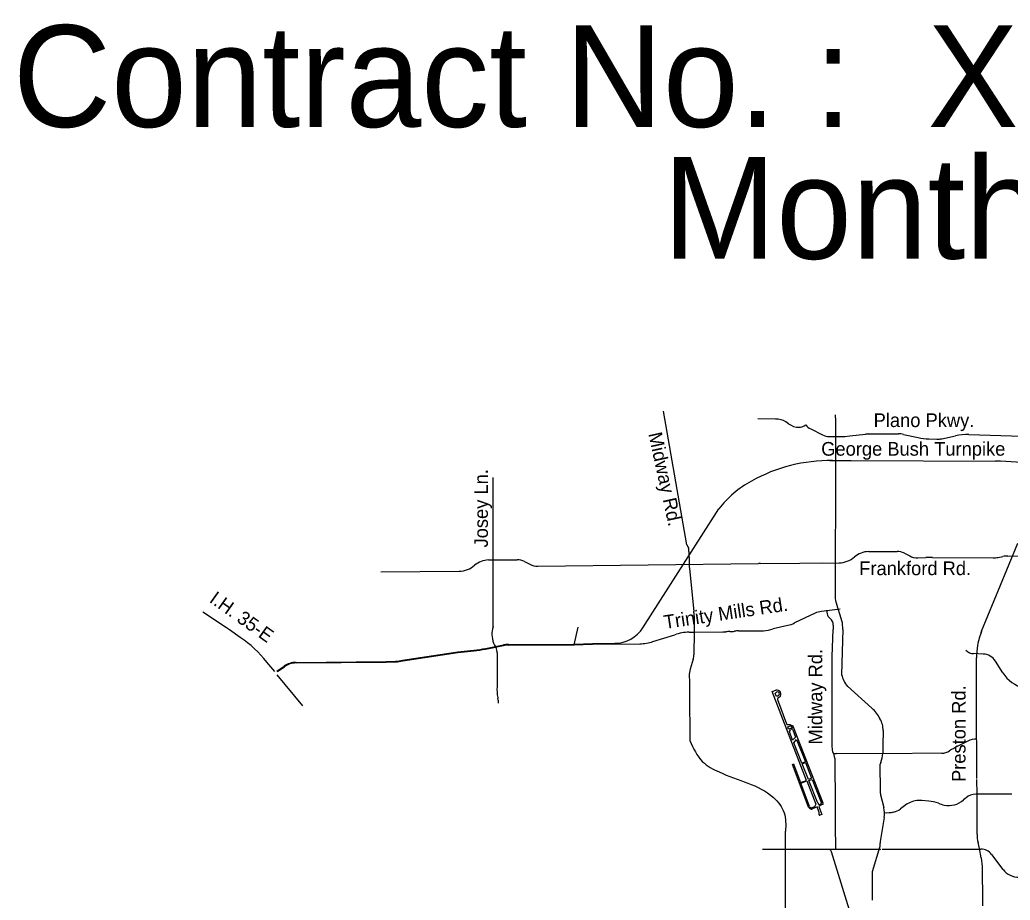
# Model space of a CAD drawing. Extents: x 105094 to 105814, y -291615 to -291123.
# Drawn here: x 105360.5 to 105448.1, y -291368.5 to -291290.6 of the extents above; entities that cross this region are included whole.
import ezdxf

# ---------------------------------------------------------------- set-up
doc = ezdxf.new("R2010")
doc.units = 0
doc.layers.add('G_BORDER', color=7, linetype='Continuous')
doc.layers.add('G_MAP', color=7, linetype='Continuous')

msp = doc.modelspace()

# ---------------------------------------------------------------- linework, layer by layer
at = {"layer": 'G_MAP'}
for p, q in [((105419.494, -291337.073), (105417.442, -291325.252)), ((105430.458, -291326.814), (105431.511, -291327.347)), ((105435.604, -291327.26), (105438.208, -291327.245)), ((105438.659, -291327.293), (105439.969, -291327.583)), ((105444.437, -291327.303), (105451.201, -291327.501)), ((105440.916, -291327.699), (105441.614, -291327.716)), ((105442.054, -291327.675), (105443.264, -291327.413)), ((105432.98, -291328.9), (105432.98, -291328.902)), ((105402.349, -291344.321), (105402.349, -291331.116)), ((105415.604, -291344.408), (105422.316, -291333.896)), ((105419.494, -291337.073), (105419.636, -291337.335)), ((105419.674, -291337.655), (105419.7, -291338.562)), ((105435.564, -291337.666), (105438.093, -291337.642)), ((105438.742, -291337.801), (105439.21, -291338.05)), ((105401.951, -291338.405), (105404.48, -291338.382)), ((105405.129, -291338.54), (105405.597, -291338.789)), ((105406.323, -291338.958), (105425.832, -291338.724)), ((105426.02, -291338.708), (105432.96, -291338.658)), ((105431.463, -291338.643), (105431.463, -291338.626)), ((105439.935, -291338.219), (105440.635, -291338.197)), ((105441.227, -291338.189), (105446.586, -291338.213)), ((105447.024, -291338.176), (105447.458, -291338.099)), ((105447.891, -291338.057), (105449.27, -291338.037)), ((105392.407, -291339.447), (105399.347, -291339.397)), ((105419.716, -291339.166), (105420.114, -291342.961)), ((105378.755, -291344.414), (105376.682, -291343.031)), ((105430.841, -291343.124), (105429.009, -291343.982)), ((105433.058, -291342.746), (105431.403, -291342.961)), ((105431.857, -291342.859), (105431.917, -291343.182)), ((105379.03, -291344.591), (105378.755, -291344.414)), ((105379.983, -291345.256), (105379.03, -291344.591)), ((105402.364, -291344.282), (105402.349, -291344.321)), ((105424.066, -291344.676), (105426.265, -291344.669)), ((105428.417, -291344.189), (105427.142, -291344.492)), ((105432.441, -291344.179), (105432.427, -291344.549)), ((105433.294, -291344.567), (105433.191, -291348.542)), ((105445.578, -291344.69), (105445.527, -291344.888)), ((105402.254, -291345.03), (105402.293, -291345.395)), ((105416.496, -291345.633), (105418.423, -291345.016)), ((105401.672, -291346.239), (105403.264, -291345.926)), ((105401.682, -291346.294), (105403.275, -291345.98)), ((105402.6, -291346.149), (105402.696, -291346.49)), ((105402.716, -291346.633), (105402.71, -291349.633)), ((105403.72, -291345.889), (105409.47, -291345.848)), ((105383.031, -291348.279), (105382.331, -291347.446)), ((105420.065, -291347.178), (105419.79, -291348.071)), ((105445.715, -291346.727), (105444.865, -291346.693)), ((105447.448, -291348.381), (105446.796, -291347.35)), ((105383.232, -291348.24), (105383.858, -291347.801)), ((105383.264, -291348.286), (105383.89, -291347.846)), ((105432.318, -291347.86), (105432.331, -291354.963)), ((105385.508, -291351.319), (105383.251, -291348.557)), ((105433.702, -291349.581), (105435.874, -291351.523)), ((105402.761, -291350.566), (105402.782, -291350.67)), ((105427.541, -291350.433), (105427.422, -291350.472)), ((105427.52, -291350.755), (105428.318, -291352.915)), ((105427.69, -291350.534), (105427.554, -291350.639)), ((105444.36, -291354.426), (105443.47, -291354.881)), ((105432.443, -291355.491), (105432.521, -291355.665)), ((105432.585, -291355.928), (105432.608, -291360.209)), ((105436.638, -291359.191), (105436.915, -291360.317)), ((105440.894, -291359.739), (105440.282, -291359.689)), ((105444.202, -291359.452), (105443.984, -291359.641)), ((105445.187, -291359.13), (105445.063, -291359.13)), ((105448.239, -291359.14), (105445.184, -291359.13)), ((105432.608, -291360.209), (105432.608, -291360.374)), ((105438.863, -291360.071), (105438.399, -291360.433)), ((105436.95, -291361.199), (105436.607, -291363.311)), ((105428.23, -291378.214), (105428.23, -291362.41)), ((105436.572, -291363.758), (105435.884, -291365.99)), ((105436.461, -291363.988), (105436.655, -291363.988)), ((105436.771, -291363.988), (105445.52, -291363.994)), ((105445.391, -291363.946), (105445.258, -291363.408)), ((105445.549, -291364.748), (105445.391, -291363.946)), ((105446.444, -291364.452), (105447.466, -291365.791)), ((105445.668, -291368.473), (105445.656, -291365.798)), ((105435.884, -291365.99), (105435.896, -291368.505)), ((105445.671, -291369), (105445.668, -291368.473))]:
    msp.add_line(p, q, dxfattribs=at)
for points in [[(105432.662, -291329.616), (105432.662, -291329.562), (105432.665, -291326.107), (105432.663, -291325.966), (105432.649, -291325.725), (105432.632, -291325.575)], [(105427.346, -291325.941), (105425.781, -291325.923)], [(105428.497, -291326.355), (105428.261, -291326.198)], [(105429.864, -291326.536), (105430.009, -291326.442)], [(105432.092, -291327.483), (105433.134, -291327.474), (105433.483, -291327.47), (105433.919, -291327.43), (105435.288, -291327.278)], [(105432.133, -291329.614), (105432.609, -291329.616), (105432.662, -291329.616)], [(105432.76, -291342.338), (105432.753, -291342.316), (105432.708, -291342.149), (105432.676, -291341.979), (105432.657, -291341.807), (105432.651, -291341.634), (105432.662, -291329.669), (105432.662, -291329.616)], [(105432.662, -291329.616), (105432.715, -291329.616), (105434.044, -291329.62)], [(105434.044, -291329.62), (105446.789, -291329.663)], [(105447.815, -291339.275), (105448.782, -291336.933)], [(105445.578, -291344.69), (105447.815, -291339.275)], [(105433.293, -291344.555), (105433.294, -291344.547), (105433.293, -291344.354), (105433.279, -291344.162), (105433.252, -291343.972), (105433.212, -291343.784), (105433.16, -291343.598), (105432.76, -291342.338)], [(105420.13, -291343.348), (105420.13, -291344.76), (105420.107, -291346.788)], [(105403.72, -291345.945), (105409.514, -291345.903), (105409.879, -291344.343)], [(105419.695, -291344.796), (105420.149, -291344.782), (105422.677, -291344.765)], [(105432.425, -291344.557), (105432.331, -291346.939)], [(105433.293, -291344.559), (105433.293, -291344.559), (105433.293, -291344.557), (105433.293, -291344.555)], [(105409.513, -291345.847), (105411.134, -291345.796), (105413.233, -291345.78)], [(105394.346, -291347.275), (105399.23, -291346.542), (105400.659, -291346.384)], [(105394.354, -291347.33), (105399.238, -291346.597), (105400.665, -291346.439)], [(105409.514, -291345.903), (105411.136, -291345.851), (105415.333, -291345.82)], [(105384.917, -291347.462), (105392.877, -291347.397), (105393.723, -291347.368)], [(105384.918, -291347.517), (105392.878, -291347.453), (105393.725, -291347.424)], [(105445.158, -291357.729), (105445.129, -291350.956), (105445.119, -291347.071)], [(105419.712, -291348.675), (105419.729, -291349.084), (105419.729, -291350.188), (105419.757, -291354.387)], [(105430.077, -291357.91), (105427.047, -291350.046), (105427.372, -291349.937)], [(105427.422, -291350.472), (105427.319, -291350.224), (105427.359, -291350.157)], [(105428.39, -291352.966), (105428.62, -291352.966), (105428.878, -291353.066), (105429.266, -291354.08), (105431.539, -291359.89), (105431.507, -291359.896), (105431.543, -291360.003), (105431.359, -291360.109), (105431.165, -291360.206), (105431.426, -291360.929), (105431.253, -291360.995)], [(105428.494, -291353.372), (105428.426, -291353.169), (105428.654, -291353.092)], [(105428.786, -291353.166), (105428.804, -291353.247), (105428.494, -291353.372)], [(105428.846, -291354.338), (105428.565, -291353.595), (105428.663, -291353.42)], [(105428.872, -291353.434), (105429.121, -291354.07), (105428.846, -291354.338)], [(105436.854, -291353.497), (105436.83, -291354.82), (105436.83, -291355.51)], [(105442.057, -291355.506), (105436.846, -291355.552), (105432.723, -291355.532)], [(105430.377, -291360.389), (105430.248, -291360.29), (105428.846, -291356.492), (105428.943, -291356.447), (105429.553, -291358.091), (105430.077, -291357.91)], [(105436.653, -291356.316), (105436.578, -291356.53), (105436.591, -291358.793)], [(105430.336, -291360.217), (105429.573, -291358.155), (105430.102, -291357.952), (105430.897, -291360.003)], [(105431.083, -291359.924), (105430.283, -291357.929), (105430.58, -291357.816), (105431.404, -291359.909)], [(105445.168, -291362.663), (105445.168, -291360.693), (105445.187, -291359.13), (105445.158, -291357.829)], [(105430.897, -291360.003), (105430.797, -291360.245), (105430.553, -291360.323)], [(105431.191, -291360.952), (105431.191, -291360.758), (105431.016, -291360.258), (105430.626, -291360.422)], [(105432.608, -291360.374), (105432.615, -291361.866), (105432.634, -291363.972)], [(105426.188, -291363.981), (105434.42, -291363.981), (105436.461, -291363.988)], [(105436.913, -291379.063), (105436.064, -291376.473), (105432.285, -291364.23)]]:
    msp.add_lwpolyline(points, dxfattribs=at)
for points in [[(105429.666, -291356.395), (105428.95, -291354.571), (105429.198, -291354.286), (105429.98, -291356.279)], [(105430.535, -291357.703), (105430.251, -291357.816), (105429.692, -291356.45), (105430.002, -291356.337)]]:
    msp.add_lwpolyline(points, close=True, dxfattribs=at)
for centre, radius, start, end in [((105427.419, -291327.437), 1.499, 55.77746, 92.78505), ((105429.418, -291325.133), 1.531, 232.97207, 270.74215), ((105431.053, -291325.639), 1.317, 217.57709, 243.13907), ((105429.434, -291325.874), 0.789, 270.33477, 303.05767), ((105432.081, -291326.221), 1.262, 243.13895, 270.49462), ((105435.622, -291330.305), 3.045, 90.34182, 96.29946), ((105438.22, -291329.272), 2.027, 77.50382, 90.34159), ((105444.308, -291332.24), 4.939, 88.50639, 102.20368), ((105441.041, -291322.749), 4.951, 257.50371, 268.55885), ((105441.661, -291325.854), 1.863, 268.55933, 282.20382), ((105432.172, -291343.832), 14.219, 89.19692, 119.24956), ((105446.989, -291343.88), 14.219, 60.75044, 90.80308), ((105429.574, -291339.495), 9.167, 118.32846, 142.34739), ((105419.029, -291337.571), 0.651, 352.58836, 21.2338), ((105435.582, -291339.562), 1.896, 90.53918, 131.22636), ((105438.106, -291338.996), 1.354, 61.98553, 90.53899), ((105401.969, -291340.301), 1.896, 90.53918, 131.22636), ((105404.493, -291339.735), 1.354, 61.98553, 90.53899), ((105424.479, -291338.736), 4.782, 177.91, 185.15297), ((105426.028, -291339.861), 1.153, 90.40973, 99.80569), ((105432.944, -291336.552), 2.106, 270.40929, 311.22643), ((105439.89, -291336.771), 1.449, 241.98546, 271.78846), ((105441.153, -291354.782), 16.593, 89.74324, 91.78839), ((105446.597, -291335.763), 2.45, 269.74291, 280.03998), ((105447.932, -291340.775), 2.718, 90.86003, 100.03993), ((105399.332, -291337.291), 2.106, 270.40929, 311.22643), ((105406.277, -291337.51), 1.449, 241.98546, 271.78846), ((105417.138, -291343.279), 2.993, 358.67048, 6.10106), ((105431.648, -291344.849), 1.904, 97.39659, 115.09309), ((105427.704, -291341.196), 3.076, 283.39224, 295.09323), ((105432.562, -291343.064), 0.655, 190.42318, 232.33488), ((105431.721, -291344.152), 0.72, 357.88031, 52.33487), ((105403.761, -291344.87), 1.516, 158.76154, 186.08296), ((105413.098, -291342.808), 2.973, 270.43359, 327.44108), ((105419.84, -291349.437), 4.643, 91.78856, 107.77361), ((105422.727, -291342.444), 2.322, 268.76103, 275.27369), ((105423.196, -291347.504), 2.759, 87.68599, 95.3173), ((105423.335, -291342.745), 2.002, 269.21704, 281.03048), ((105424.063, -291346.441), 1.765, 89.9115, 101.27143), ((105425.962, -291340.901), 3.781, 274.59281, 288.18927), ((105451.106, -291346.932), 5.965, 157.92698, 170.6588), ((105374.649, -291353.33), 9.676, 37.44821, 56.54693), ((105403.71, -291345.245), 1.424, 186.03838, 217.81244), ((105415.303, -291341.909), 3.91, 270.43711, 287.7647), ((105398.091, -291324.778), 21.757, 276.77716, 279.47674), ((105398.091, -291324.778), 21.813, 276.77716, 279.47674), ((105402.516, -291346.173), 0.0879, 15.71493, 38.32858), ((105402.096, -291346.649), 0.62, 1.53274, 14.87021), ((105403.608, -291347.344), 1.459, 85.38668, 103.71734), ((105403.608, -291347.344), 1.403, 85.38668, 103.71734), ((105444.906, -291345.668), 1.026, 224.97149, 267.72857), ((105451.328, -291347.08), 6.209, 169.64608, 179.91923), ((105384.933, -291349.332), 1.87, 90.4703, 125.05326), ((105384.933, -291349.332), 1.815, 90.4703, 125.05326), ((105392.155, -291334.703), 12.762, 277.03378, 279.88042), ((105392.155, -291334.703), 12.817, 277.03378, 279.88042), ((105419.257, -291346.894), 0.857, 340.61628, 7.11911), ((105449.331, -291347.638), 17.014, 177.64471, 180.74489), ((105445.662, -291348.066), 1.341, 32.29893, 87.74593), ((105421.51, -291348.6), 1.799, 162.88337, 182.36845), ((105450.034, -291346.746), 3.06, 212.30227, 256.59239), ((105435.361, -291348.122), 2.209, 190.66231, 221.50454), ((105405.803, -291349.93), 3.107, 174.51673, 191.81797), ((105427.514, -291350.252), 0.181, 29.65166, 148.47563), ((105427.481, -291350.262), 0.343, 307.59837, 108.57454), ((105399.266, -291351.374), 3.586, 4.69213, 11.32859), ((105427.616, -291350.72), 0.102, 127.6658, 200.05083), ((105427.475, -291350.235), 0.208, 288.45234, 20.41756), ((105433.852, -291353.784), 3.033, 25.68157, 48.20871), ((105434.9, -291353.459), 1.955, 358.89174, 30.54093), ((105428.389, -291352.89), 0.0754, 199.47439, 270.83434), ((105428.687, -291353.188), 0.101, 12.60514, 108.73279), ((105428.764, -291353.476), 0.115, 21.35249, 150.97221), ((105445.08, -291355.835), 1.582, 87.85519, 117.05464), ((105433.637, -291354.961), 1.306, 180.12033, 203.9323), ((105442.045, -291354.221), 1.285, 270.51918, 303.03142), ((105447.196, -291362.173), 8.189, 117.06703, 122.91568), ((105432.735, -291354.017), 1.515, 259.54838, 269.55484), ((105431.816, -291355.976), 0.77, 3.55683, 23.80301), ((105434.853, -291355.498), 1.977, 335.39441, 359.64559), ((105438.217, -291358.804), 1.625, 179.62207, 193.75525), ((105440.147, -291361.917), 2.248, 93.64237, 124.82444), ((105440.044, -291361.377), 1.704, 81.99406, 91.3573), ((105440.604, -291363.32), 3.593, 71.37739, 85.37268), ((105442.671, -291358.131), 2.001, 258.18148, 311.00156), ((105445.063, -291360.444), 1.314, 90.01008, 130.9336), ((105430.5, -291360.157), 0.174, 200.29521, 287.72551), ((105430.529, -291360.191), 0.25, 232.42556, 292.79584), ((105431.241, -291359.861), 0.17, 201.83323, 343.57725), ((105434.768, -291360.845), 2.211, 350.78044, 13.81133), ((105437.55, -291359.344), 1.38, 279.93128, 307.91386), ((105442.725, -291357.899), 2.239, 244.21714, 258.04684), ((105431.237, -291360.952), 0.0461, 179.99988, 290.91002), ((105437.215, -291358.181), 2.586, 264.70939, 282.80312), ((105448.282, -291362.663), 3.114, 180.00084, 193.83905), ((105431.82, -291364.374), 0.487, 17.17228, 49.39679), ((105439.373, -291363.758), 2.801, 170.81953, 179.99321), ((105445.519, -291365.158), 1.163, 37.34704, 89.9561), ((105440.026, -291365.843), 5.631, 0.45097, 11.20641), ((105448.825, -291364.754), 1.709, 217.36211, 272.80393)]:
    msp.add_arc(centre, radius, start, end, dxfattribs=at)
msp.add_spline([(105419.757, -291354.387), (105420.892, -291356.253), (105422.349, -291357.164), (105424.897, -291358.148), (105427.154, -291359.423), (105428.101, -291360.771), (105428.23, -291362.41)], degree=3, dxfattribs=at)

# ---------------------------------------------------------------- texts
at = {"layer": 'G_BORDER'}
for s, p in [('Contract No. :  XX - XXX/XXX', (105359.866, -291300.097)), ('Month, Year', (105417.378, -291311.764))]:
    msp.add_text(s, height=9, dxfattribs=at).set_placement(p)
at = {"layer": 'G_MAP'}
for s, p in [('Plano Pkwy.', (105436.021, -291326.646)), ('George Bush Turnpike', (105431.382, -291329.18)), ('Frankford Rd.', (105434.746, -291339.75))]:
    msp.add_text(s, height=1.21107, dxfattribs=at).set_placement(p)
for s, height, rotation, p in [('Midway Rd.', 1.2111, 282.36877, (105416.079, -291327.24)), ('Josey Ln.', 1.2111, 90, (105401.892, -291337.3)), ('I.H. 35-E', 1.2111, 324.55731, (105377.166, -291342.078)), ('Trinity Mills Rd.', 1.21107, 8.51005, (105417.551, -291344.516)), ('Midway Rd.', 1.2111, 90, (105431.473, -291354.734)), ('Preston Rd.', 1.21107, 90, (105444.152, -291358.049))]:
    msp.add_text(s, height=height, rotation=rotation, dxfattribs=at).set_placement(p)

doc.saveas('drawing.dxf')
